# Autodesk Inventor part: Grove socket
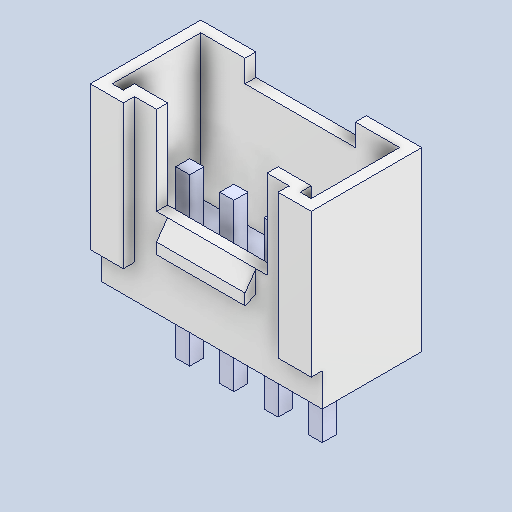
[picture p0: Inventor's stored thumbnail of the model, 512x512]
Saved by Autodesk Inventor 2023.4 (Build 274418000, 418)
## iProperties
Created: 2019-06
Part Number: Grove socket
Material: Générique
Document SubType Name: Modeling
Designer: mel
Density: 1 g/cm^3
Appearance: Par défaut
Author: mel
Sending System: SolidWorks 2018
Last Author: Hazel
Last Saved: 2019-07-09
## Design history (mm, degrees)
feature "Boss-Extrude4"
node "Plane1"
node "Solide1"
